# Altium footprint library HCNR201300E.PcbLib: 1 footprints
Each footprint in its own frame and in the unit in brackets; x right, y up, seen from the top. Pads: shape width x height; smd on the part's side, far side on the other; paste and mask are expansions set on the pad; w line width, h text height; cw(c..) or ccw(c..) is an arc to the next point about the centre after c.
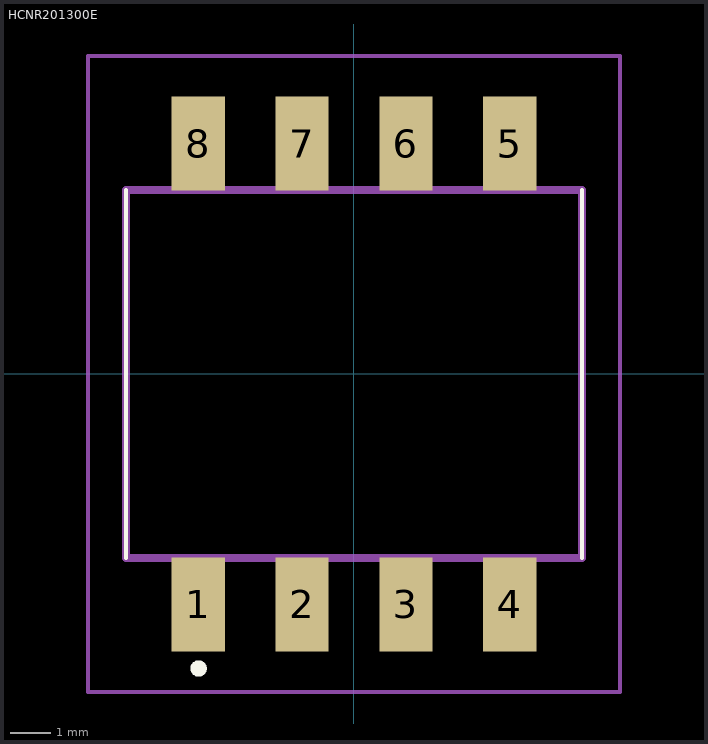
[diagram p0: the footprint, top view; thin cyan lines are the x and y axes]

## HCNR201300E [mm]
pads (8):
  rect 1.3x2.29 smd: 1(-3.81,-5.635) 2(-1.27,-5.635) 3(1.27,-5.635) 4(3.81,-5.635) 5(3.81,5.635) 6(1.27,5.635) 7(-1.27,5.635) 8(-3.81,5.635)
Top Overlay:
  lines w0.1: -5.575,-4.5 -5.575,4.5 ; 5.575,-4.5 5.575,4.5
  lines w0.2: -3.9,-7.2 -3.9,-7.2 ; -3.9,-7.2 ccw(c-3.8,-7.2) -3.7,-7.2 ; -3.9,-7.2 cw(c-3.8,-7.2) -3.7,-7.2 ; -3.7,-7.2 -3.7,-7.2
Mechanical 15:
  lines w0.2: -5.575,-4.5 5.575,-4.5 5.575,4.5 -5.575,4.5 -5.575,-4.5
Mechanical 20:
  lines w0.1: -6.5,-7.78 6.5,-7.78 6.5,7.78 -6.5,7.78 -6.5,-7.78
